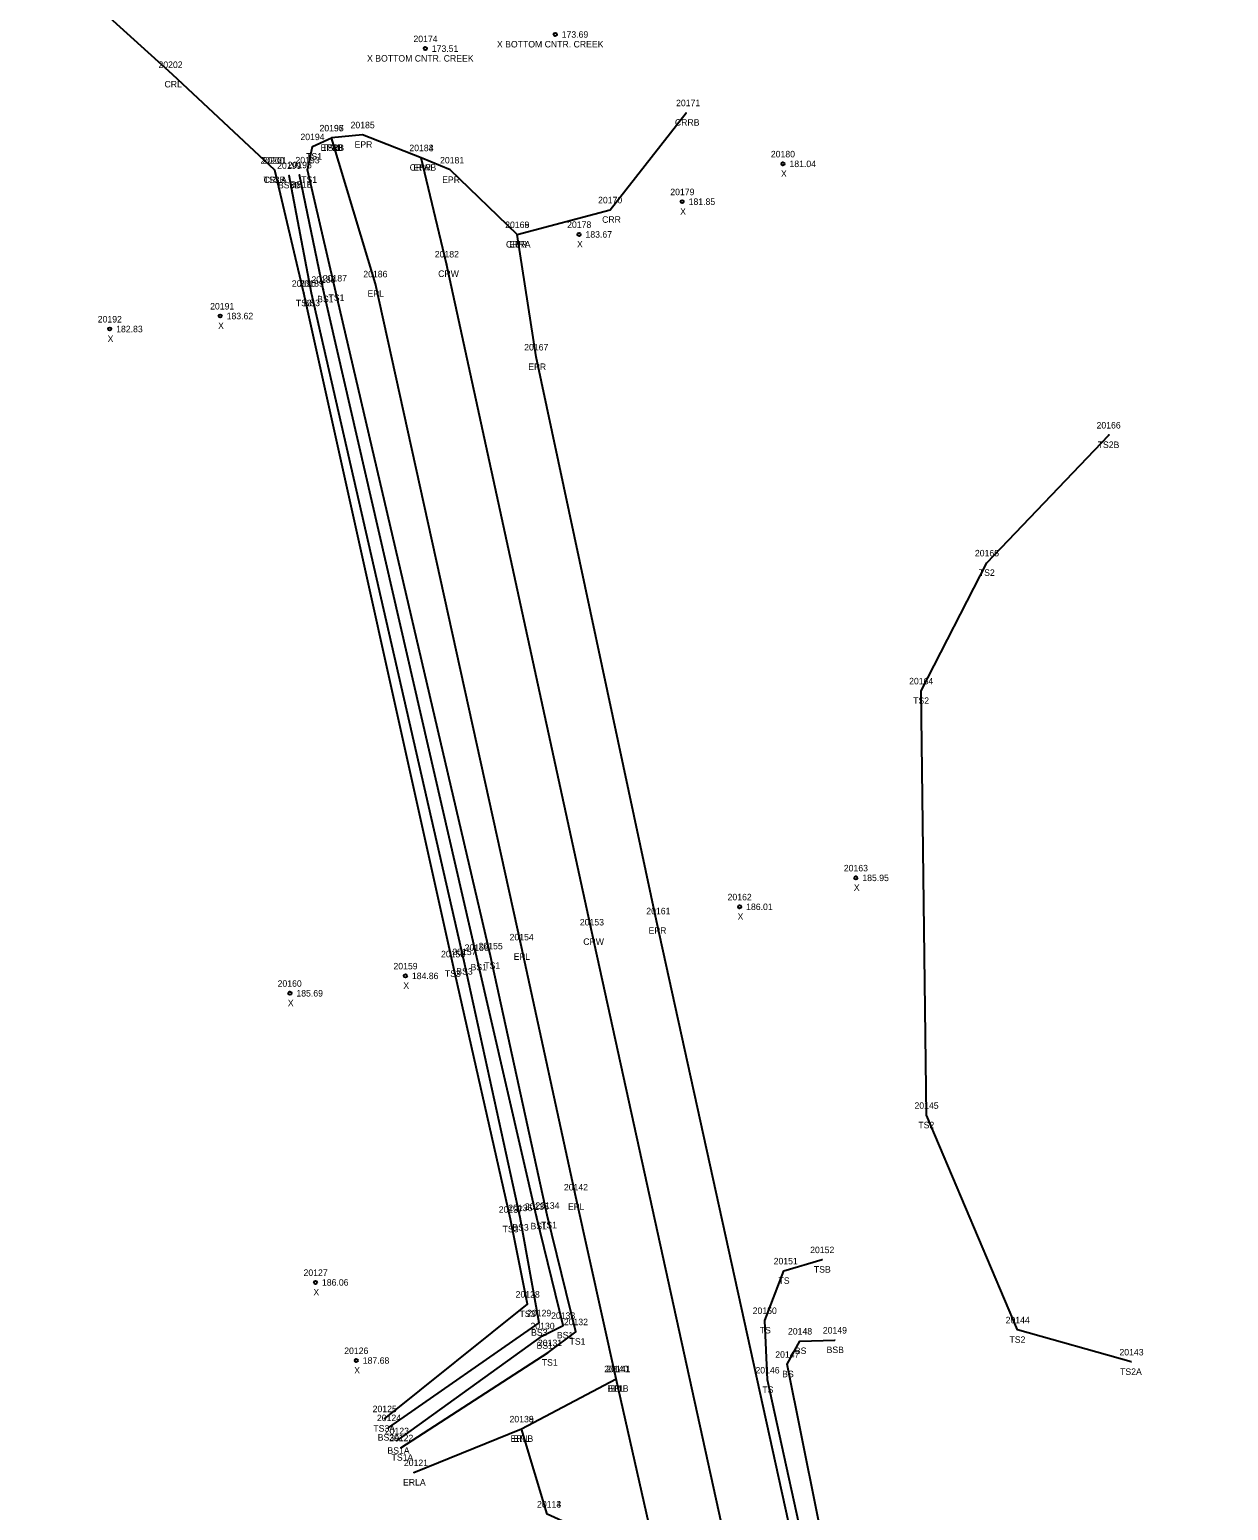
# Model space of a CAD drawing. Extents: x 2077883 to 2078272, y 787819 to 788945.
# Drawn here: x 2078043.7 to 2078228.5, y 788152.9 to 788381 of the extents above; entities that cross this region are included whole.
import ezdxf

# ---------------------------------------------------------------- set-up
doc = ezdxf.new("R2010")
doc.units = 0
for name, color, linetype in [('RD_DTM_BkLn1', 7, 'Continuous'), ('RD_DTM_BkLn2', 7, 'Continuous'), ('RD_EX_H2O', 7, 'Continuous'), ('RD_EX_H2O_txCode', 7, 'Continuous'), ('RD_EX_Road', 7, 'Continuous'), ('RD_EX_Road_txCode', 7, 'Continuous'), ('RD_Sketch8', 7, 'Continuous'), ('RD_SMD_Locator', 7, 'Continuous'), ('RD_SMD_Misc', 7, 'Continuous')]:
    doc.layers.add(name, color=color, linetype=linetype)

msp = doc.modelspace()

# ---------------------------------------------------------------- linework, layer by layer
at = {"layer": 'RD_DTM_BkLn1'}
msp.add_line((2078141.74, 788139.37), (2078134.14, 788173.23), dxfattribs=at)
msp.add_lwpolyline([(2078218.47, 787830.39), (2078196.8, 787935.53), (2078175.25, 788036.87), (2078153.19, 788138.02), (2078130.35, 788242.05), (2078107.99, 788344.95), (2078104.08, 788361.32)], dxfattribs=at)
at = {"layer": 'RD_DTM_BkLn2'}
for points in [[(2078100.95, 788162.6), (2078123.61, 788177.24), (2078127.89, 788180.47), (2078123.5, 788198.4), (2078114.75, 788238.37), (2078090.74, 788341.25), (2078086.53, 788359.44), (2078087.29, 788363.02), (2078090.24, 788364.37)], [(2078098.42, 788167.07), (2078120.45, 788184.72), (2078117.85, 788197.78), (2078108.95, 788237.14), (2078086, 788340.43), (2078081.49, 788359.41)], [(2078099.08, 788165.69), (2078122.23, 788181.84), (2078119.34, 788198.04), (2078110.7, 788237.48), (2078087.16, 788340.45), (2078083.69, 788358.59)], [(2078100.3, 788163.67), (2078122.78, 788179.84), (2078125.93, 788181.44), (2078121.86, 788198.24), (2078112.62, 788238.13), (2078088.97, 788341.04), (2078085.31, 788358.7)], [(2078213.52, 788175.81), (2078195.98, 788180.76), (2078181.94, 788213.8), (2078181.13, 788279.19), (2078191.27, 788298.9), (2078210.04, 788318.6)], [(2078196.71, 788020.24), (2078187.64, 788040.54), (2078164.48, 788140.93), (2078157.44, 788173.03), (2078157.04, 788182.2), (2078159.94, 788189.84), (2078165.86, 788191.57)], [(2078197.77, 788027.29), (2078194.88, 788040.23), (2078167.29, 788141.5), (2078160.48, 788175.45), (2078162.44, 788179.03), (2078167.8, 788179.18)]]:
    msp.add_lwpolyline(points, dxfattribs=at)
at = {"layer": 'RD_EX_H2O'}
for points in [[(2078081.49, 788359.41), (2078065.72, 788374.14), (2078043.71, 788394.09)], [(2078118.87, 788349.48), (2078133.21, 788353.29), (2078144.9, 788368.25)]]:
    msp.add_lwpolyline(points, dxfattribs=at)
at = {"layer": 'RD_EX_Road'}
msp.add_line((2078102.95, 788158.77), (2078119.52, 788165.5), dxfattribs=at)
for points in [[(2078228.48, 787832.26), (2078206.7, 787937.94), (2078195.2, 787994.28), (2078202.14, 788002.84), (2078209.52, 788006.82), (2078218.3, 788009.13), (2078214.45, 788022.16), (2078205.73, 788019.64), (2078196.71, 788020.24), (2078189.11, 788024.39), (2078185.07, 788039.81), (2078163.11, 788140.18), (2078140.34, 788243.77), (2078121.8, 788330.62), (2078118.87, 788349.48), (2078108.52, 788359.43), (2078104.08, 788361.32), (2078095.01, 788364.85), (2078090.24, 788364.37)], [(2078207.78, 787828.19), (2078186.33, 787933.07), (2078181.72, 787953.57), (2078178.38, 787956.37), (2078173.08, 787956.24), (2078168.39, 787955.22), (2078162.37, 787970.77), (2078170.31, 787975.52), (2078175.69, 787980.93), (2078164.7, 788034.41), (2078142.62, 788135.61), (2078141.74, 788139.37), (2078130.94, 788148.94), (2078127.54, 788150.51), (2078123.47, 788152.38), (2078119.52, 788165.5), (2078134.14, 788173.23), (2078127.9, 788201.23), (2078119.52, 788239.75), (2078097, 788341.89), (2078090.24, 788364.37)]]:
    msp.add_lwpolyline(points, dxfattribs=at)
at = {"layer": 'RD_SMD_Locator'}
for centre, radius in [((2078124.72, 788380.3), 0.25), ((2078104.7, 788378.12), 0.25), ((2078065.72, 788374.14), 0.001), ((2078144.9, 788368.25), 0.001), ((2078090.24, 788364.37), 0.001), ((2078090.24, 788364.37), 0.001), ((2078090.24, 788364.37), 0.001), ((2078095.01, 788364.85), 0.001), ((2078087.29, 788363.02), 0.001), ((2078104.08, 788361.32), 0.001), ((2078104.08, 788361.32), 0.001), ((2078081.49, 788359.41), 0.001), ((2078081.49, 788359.41), 0.001), ((2078086.53, 788359.44), 0.001), ((2078108.52, 788359.43), 0.001), ((2078159.83, 788360.37), 0.25), ((2078083.69, 788358.59), 0.001), ((2078085.31, 788358.7), 0.001), ((2078144.29, 788354.54), 0.25), ((2078133.21, 788353.29), 0.001), ((2078118.87, 788349.48), 0.001), ((2078118.87, 788349.48), 0.001), ((2078128.39, 788349.5), 0.25), ((2078107.99, 788344.95), 0.001), ((2078088.97, 788341.04), 0.001), ((2078090.74, 788341.25), 0.001), ((2078097, 788341.89), 0.001), ((2078086, 788340.43), 0.001), ((2078087.16, 788340.45), 0.001), ((2078073.08, 788336.93), 0.25), ((2078056.05, 788334.93), 0.25), ((2078121.8, 788330.62), 0.001), ((2078210.04, 788318.6), 0.001), ((2078191.27, 788298.9), 0.001), ((2078181.13, 788279.19), 0.001), ((2078171.06, 788250.38), 0.25), ((2078153.15, 788245.92), 0.25), ((2078140.34, 788243.77), 0.001), ((2078130.35, 788242.05), 0.001), ((2078112.62, 788238.13), 0.001), ((2078114.75, 788238.37), 0.001), ((2078119.52, 788239.75), 0.001), ((2078108.95, 788237.14), 0.001), ((2078110.7, 788237.48), 0.001), ((2078101.63, 788235.28), 0.25), ((2078083.83, 788232.6), 0.25), ((2078181.94, 788213.8), 0.001), ((2078127.9, 788201.23), 0.001), ((2078117.85, 788197.78), 0.001), ((2078119.34, 788198.04), 0.001), ((2078121.86, 788198.24), 0.001), ((2078123.5, 788198.4), 0.001), ((2078165.86, 788191.57), 0.001), ((2078087.77, 788188.06), 0.25), ((2078159.94, 788189.84), 0.001), ((2078120.45, 788184.72), 0.001), ((2078122.23, 788181.84), 0.001), ((2078125.93, 788181.44), 0.001), ((2078157.04, 788182.2), 0.001), ((2078122.78, 788179.84), 0.001), ((2078127.89, 788180.47), 0.001), ((2078162.44, 788179.03), 0.001), ((2078167.8, 788179.18), 0.001), ((2078195.98, 788180.76), 0.001), ((2078123.61, 788177.24), 0.001), ((2078094.06, 788176.03), 0.25), ((2078160.48, 788175.45), 0.001), ((2078213.52, 788175.81), 0.001), ((2078134.14, 788173.23), 0.001), ((2078134.14, 788173.23), 0.001), ((2078157.44, 788173.03), 0.001), ((2078098.42, 788167.07), 0.001), ((2078099.08, 788165.69), 0.001), ((2078119.52, 788165.5), 0.001), ((2078119.52, 788165.5), 0.001), ((2078100.3, 788163.67), 0.001), ((2078100.95, 788162.6), 0.001), ((2078102.95, 788158.77), 0.001)]:
    msp.add_circle(centre, radius, dxfattribs=at)

# ---------------------------------------------------------------- texts
at = {"layer": 'RD_EX_H2O_txCode'}
for s, p in [('20202', (2078063.57, 788375.14)), ('CRL', (2078064.5, 788372.14)), ('20171', (2078143.35, 788369.25)), ('CRRB', (2078143.17, 788366.25)), ('20201', (2078079.61, 788360.41)), ('CRLA', (2078079.77, 788357.41)), ('20170', (2078131.33, 788354.29)), ('CRR', (2078131.95, 788351.29)), ('20169', (2078117.01, 788350.48)), ('CRRA', (2078117.13, 788347.48))]:
    msp.add_text(s, height=1, dxfattribs=at).set_placement(p)
at = {"layer": 'RD_EX_Road_txCode'}
for s, p in [('20196', (2078088.38, 788365.37)), ('20197', (2078088.4, 788365.37)), ('20185', (2078093.18, 788365.85)), ('EPR', (2078093.79, 788362.85)), ('EPRB', (2078088.54, 788362.37)), ('EPLB', (2078088.56, 788362.37)), ('20184', (2078102.24, 788362.32)), ('20181', (2078106.97, 788360.43)), ('EPR', (2078102.85, 788359.32)), ('EPR', (2078107.29, 788357.43)), ('20168', (2078117.01, 788350.48)), ('EPR', (2078117.64, 788347.48)), ('20186', (2078095.14, 788342.89)), ('EPL', (2078095.79, 788339.89)), ('20167', (2078119.94, 788331.62)), ('EPR', (2078120.57, 788328.62)), ('20161', (2078138.76, 788244.77)), ('EPR', (2078139.11, 788241.77)), ('20154', (2078117.69, 788240.75)), ('EPL', (2078118.32, 788237.75)), ('20142', (2078126.06, 788202.23)), ('EPL', (2078126.69, 788199.23)), ('20140', (2078132.27, 788174.23)), ('EPL', (2078132.94, 788171.23)), ('20138', (2078117.68, 788166.5)), ('20139', (2078117.68, 788166.5)), ('ERLB', (2078117.84, 788163.5)), ('EPL', (2078118.31, 788163.5)), ('20121', (2078101.4, 788159.77)), ('ERLA', (2078101.26, 788156.77)), ('20113', (2078121.92, 788153.38)), ('20114', (2078121.92, 788153.38))]:
    msp.add_text(s, height=1, dxfattribs=at).set_placement(p)
at = {"layer": 'RD_Sketch8'}
for s, p in [('20174', (2078102.87, 788379.12)), ('173.69', (2078125.72, 788379.8)), ('173.51', (2078105.7, 788377.62)), ('X BOTTOM CNTR. CREEK', (2078115.74, 788378.3)), ('X BOTTOM CNTR. CREEK', (2078095.72, 788376.12)), ('20180', (2078157.96, 788361.37)), ('X', (2078159.52, 788358.37)), ('181.04', (2078160.83, 788359.87)), ('20179', (2078142.46, 788355.54)), ('181.85', (2078145.29, 788354.04)), ('X', (2078143.98, 788352.54)), ('20178', (2078126.56, 788350.5)), ('183.67', (2078129.39, 788349)), ('X', (2078128.08, 788347.5)), ('20191', (2078071.53, 788337.93)), ('20192', (2078054.21, 788335.93)), ('183.62', (2078074.08, 788336.43)), ('X', (2078055.73, 788332.93)), ('182.83', (2078057.05, 788334.43)), ('X', (2078072.76, 788334.93)), ('20163', (2078169.21, 788251.38)), ('185.95', (2078172.06, 788249.88)), ('20162', (2078151.29, 788246.92)), ('X', (2078170.75, 788248.38)), ('186.01', (2078154.15, 788245.42)), ('X', (2078152.83, 788243.92)), ('20159', (2078099.79, 788236.28)), ('20160', (2078081.93, 788233.6)), ('X', (2078101.31, 788233.28)), ('184.86', (2078102.63, 788234.78)), ('X', (2078083.51, 788230.6)), ('185.69', (2078084.83, 788232.1)), ('20127', (2078085.93, 788189.06)), ('186.06', (2078088.77, 788187.56)), ('X', (2078087.45, 788186.06)), ('20126', (2078092.2, 788177.03)), ('187.68', (2078095.06, 788175.53)), ('X', (2078093.74, 788174.03))]:
    msp.add_text(s, height=1, dxfattribs=at).set_placement(p)
at = {"layer": 'RD_SMD_Misc'}
for s, p in [('20195', (2078088.4, 788365.37)), ('20194', (2078085.45, 788364.02)), ('20200', (2078079.29, 788360.41)), ('20193', (2078084.69, 788360.44)), ('TS1', (2078086.33, 788361.02)), ('TS1B', (2078088.8, 788362.37)), ('20183', (2078102.24, 788362.32)), ('20199', (2078081.86, 788359.59)), ('20198', (2078083.48, 788359.7)), ('CRWB', (2078102.29, 788359.32)), ('TS3B', (2078079.77, 788357.41)), ('BS3B', (2078081.99, 788356.59)), ('BS1B', (2078083.89, 788356.7)), ('TS1', (2078085.57, 788357.44)), ('20182', (2078106.16, 788345.95)), ('20188', (2078087.14, 788342.04)), ('20187', (2078088.9, 788342.25)), ('CRW', (2078106.68, 788342.95)), ('20190', (2078084.12, 788341.43)), ('20189', (2078085.33, 788341.45)), ('TS3', (2078084.75, 788338.43)), ('BS3', (2078085.93, 788338.45)), ('BS1', (2078088.03, 788339.04)), ('TS1', (2078089.78, 788339.25)), ('20166', (2078208.16, 788319.6)), ('TS2B', (2078208.33, 788316.6)), ('20165', (2078189.41, 788299.9)), ('TS2', (2078190.02, 788296.9)), ('20164', (2078179.27, 788280.19)), ('TS2', (2078179.89, 788277.19)), ('20153', (2078128.52, 788243.05)), ('20155', (2078112.91, 788239.37)), ('CRW', (2078129.04, 788240.05)), ('20158', (2078107.12, 788238.14)), ('20157', (2078108.86, 788238.48)), ('20156', (2078110.76, 788239.13)), ('TS3', (2078107.71, 788235.14)), ('BS3', (2078109.47, 788235.48)), ('BS1', (2078111.67, 788236.13)), ('TS1', (2078113.79, 788236.37)), ('20145', (2078180.1, 788214.8)), ('TS2', (2078180.69, 788211.8)), ('20137', (2078116.02, 788198.78)), ('20136', (2078117.48, 788199.04)), ('20135', (2078120.03, 788199.24)), ('20134', (2078121.66, 788199.4)), ('BS3', (2078118.11, 788196.04)), ('BS1', (2078120.92, 788196.24)), ('TS1', (2078122.54, 788196.4)), ('TS3', (2078116.61, 788195.78)), ('20152', (2078164.02, 788192.57)), ('20151', (2078158.39, 788190.84)), ('TSB', (2078164.59, 788189.57)), ('TS', (2078159.14, 788187.84)), ('20128', (2078118.62, 788185.72)), ('TS3', (2078119.21, 788182.72)), ('20129', (2078120.39, 788182.84)), ('20133', (2078124.09, 788182.44)), ('20150', (2078155.16, 788183.2)), ('20130', (2078120.91, 788180.84)), ('20132', (2078126.05, 788181.47)), ('TS', (2078156.24, 788180.2)), ('20149', (2078165.97, 788180.18)), ('20144', (2078194.15, 788181.76)), ('BS3', (2078121, 788179.84)), ('BS1', (2078121.84, 788177.84)), ('20131', (2078122.06, 788178.24)), ('BS1', (2078124.98, 788179.44)), ('TS1', (2078126.93, 788178.47)), ('20148', (2078160.6, 788180.03)), ('TS2', (2078194.74, 788178.76)), ('20147', (2078158.64, 788176.45)), ('BS', (2078161.66, 788177.03)), ('BSB', (2078166.55, 788177.18)), ('20143', (2078211.69, 788176.81)), ('TS1', (2078122.65, 788175.24)), ('20141', (2078132.59, 788174.23)), ('20146', (2078155.59, 788174.03)), ('BS', (2078159.7, 788173.45)), ('TS2A', (2078211.79, 788173.81)), ('BL1B', (2078132.75, 788171.23)), ('TS', (2078156.65, 788171.03)), ('20125', (2078096.58, 788168.07)), ('20124', (2078097.24, 788166.69)), ('TS3A', (2078096.69, 788165.07)), ('20123', (2078098.46, 788164.67)), ('BS3A', (2078097.36, 788163.69)), ('20122', (2078099.12, 788163.6)), ('BS1A', (2078098.86, 788161.67)), ('TS1A', (2078099.5, 788160.6))]:
    msp.add_text(s, height=1, dxfattribs=at).set_placement(p)

doc.saveas('drawing.dxf')
